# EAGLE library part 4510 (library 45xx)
BCD up down COUNTER
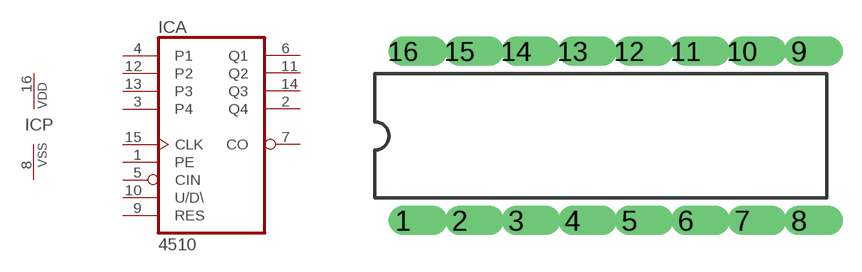
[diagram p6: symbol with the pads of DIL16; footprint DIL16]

Designator prefix IC; gates A=4510 P=PWRN

## 4510N  [DIL16]
1  A:PE  in
2  A:Q4  out
3  A:P4  in
4  A:P1  in
5  A:CIN  in
6  A:Q1  out
7  A:CO  out
8  P:VSS  pwr
9  A:RES  in
10  A:U/D\  in
11  A:Q2  out
12  A:P2  in
13  A:P3  in
14  A:Q3  out
15  A:CLK  in
16  P:VDD  pwr

## Footprint DIL16 (pad centres in mm)
Dual In Line
drill 0.813 offset: 1 -8.89,-3.81; 2 -6.35,-3.81; 3 -3.81,-3.81; 4 -1.27,-3.81; 5 1.27,-3.81; 6 3.81,-3.81; 7 6.35,-3.81; 8 8.89,-3.81; 9 8.89,3.81; 10 6.35,3.81; 11 3.81,3.81; 12 1.27,3.81; 13 -1.27,3.81; 14 -3.81,3.81; 15 -6.35,3.81; 16 -8.89,3.81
